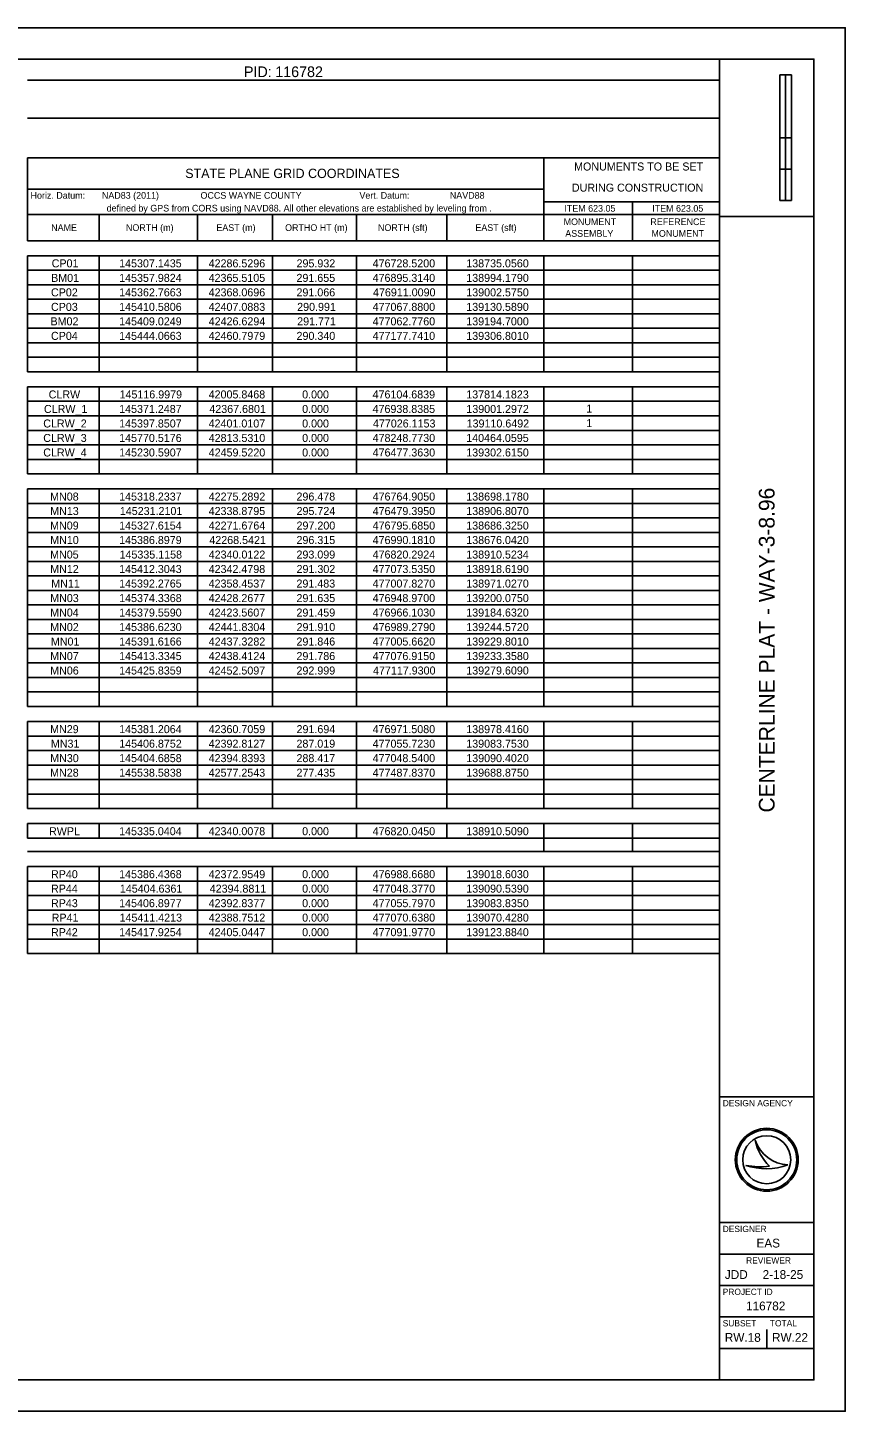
# Model space of a CAD drawing. Extents: x 0 to 34, y 0 to 22.
# Drawn here: x 21 to 34, y 0 to 22 of the extents above; entities that cross this region are included whole.
import ezdxf

# ---------------------------------------------------------------- set-up
doc = ezdxf.new("R2010")
doc.units = 0
for name, color, linetype in [('SH_Border', 7, 'Continuous'), ('SH_Cut_Line', 7, 'Continuous'), ('SH_Data', 7, 'Continuous'), ('SH_Text', 7, 'Continuous')]:
    doc.layers.add(name, color=color, linetype=linetype)

msp = doc.modelspace()

# ---------------------------------------------------------------- linework, layer by layer
at = {"layer": 'SH_Border'}
for p, q in [((32, 0.5), (32, 21.5)), ((32, 19), (33.5, 19)), ((32, 5), (33.5, 5)), ((32, 3), (33.5, 3)), ((32, 2.5), (33.5, 2.5)), ((32, 2), (33.5, 2)), ((32, 1.5), (33.5, 1.5)), ((32, 1), (33.5, 1))]:
    msp.add_line(p, q, dxfattribs=at)
msp.add_lwpolyline([(1.5, 21.5), (33.5, 21.5), (33.5, 0.5), (1.5, 0.5)], close=True, dxfattribs=at)
at = {"layer": 'SH_Cut_Line'}
msp.add_lwpolyline([(0, 0), (34, 0), (34, 22), (0, 22)], close=True, dxfattribs=at)
at = {"layer": 'SH_Data'}
for p, q in [((32.957, 19.25), (32.957, 21.25)), ((33.144, 21.25), (32.957, 21.25)), ((32.957, 20.25), (32.957, 21.25)), ((32.957, 21.25), (33.05, 21.25)), ((33.05, 21.25), (33.051, 21.25)), ((33.051, 21.25), (33.051, 20.25)), ((33.144, 21.25), (33.144, 19.25)), ((33.051, 20.25), (32.957, 20.25)), ((33.143, 20.25), (33.05, 20.25)), ((33.05, 20.25), (33.05, 19.75)), ((33.143, 19.75), (33.143, 20.25)), ((33.05, 19.75), (32.957, 19.75)), ((32.957, 19.75), (32.957, 19.25)), ((33.05, 19.75), (33.143, 19.75)), ((33.05, 19.25), (33.05, 19.75)), ((33.144, 19.25), (32.957, 19.25)), ((32.957, 19.25), (33.05, 19.25)), ((32.567, 4.31), (32.567, 4.31)), ((32.75, 4), (32.75, 4)), ((32.417, 3.91), (32.417, 3.91)), ((33.087, 3.919), (33.087, 3.919)), ((32.75, 1), (32.75, 1.3))]:
    msp.add_line(p, q, dxfattribs=at)
for radius in [0.5, 0.477, 0.477, 0.382]:
    msp.add_circle((32.75, 4), radius, dxfattribs=at)
for centre, radius, start, end in [((33.116, 4.498), 0.58, 198.9257, 198.9319), ((33.347, 4.47), 0.796, 191.6379, 191.6421), ((33.116, 4.498), 0.58, 198.9319, 267.1657), ((33.347, 4.47), 0.796, 191.6421, 226.0947), ((32.739, 4.87), 1.013, 251.4576, 290.0832), ((32.648, 5.154), 1.266, 259.4964, 259.4995), ((32.739, 4.87), 1.013, 251.4527, 251.4576), ((32.648, 5.154), 1.266, 259.4995, 276.6672)]:
    msp.add_arc(centre, radius, start, end, dxfattribs=at)
at = {"layer": 'SH_Text'}
for p, q in [((20.997, 21.168), (22.132, 21.168)), ((22.132, 21.168), (32, 21.168)), ((32, 21.168), (32, 19.932)), ((20.997, 20.559), (22.132, 20.559)), ((22.132, 20.559), (32, 20.559)), ((20.997, 19.932), (22.132, 19.932)), ((20.997, 19.932), (20.997, 19.028)), ((22.132, 19.932), (32, 19.932)), ((29.205, 19.932), (29.205, 19.028)), ((32, 19.932), (32, 19.028)), ((20.997, 19.434), (22.132, 19.434)), ((22.132, 19.434), (29.205, 19.434)), ((29.205, 19.231), (32, 19.231)), ((30.617, 19.231), (30.617, 19.028)), ((20.997, 19.028), (22.132, 19.028)), ((20.997, 19.028), (20.997, 18.613)), ((22.132, 19.028), (32, 19.028)), ((22.132, 19.028), (22.132, 18.613)), ((23.699, 19.028), (23.699, 18.613)), ((24.889, 19.028), (24.889, 18.613)), ((26.226, 19.028), (26.226, 18.613)), ((27.665, 19.028), (27.665, 18.613)), ((29.205, 19.028), (29.205, 18.613)), ((30.617, 19.028), (30.617, 18.613)), ((32, 19.028), (32, 17.451)), ((20.997, 18.613), (22.132, 18.613)), ((22.132, 18.613), (32, 18.613)), ((20.997, 18.373), (22.132, 18.373)), ((20.997, 18.373), (20.997, 17.451)), ((22.132, 18.373), (32, 18.373)), ((22.132, 18.373), (22.132, 17.451)), ((23.699, 18.373), (23.699, 17.451)), ((24.889, 18.373), (24.889, 17.451)), ((26.226, 18.373), (26.226, 17.451)), ((27.665, 18.373), (27.665, 17.451)), ((29.205, 18.373), (29.205, 17.451)), ((30.617, 18.373), (30.617, 17.451)), ((20.997, 18.143), (22.132, 18.143)), ((22.132, 18.143), (32, 18.143)), ((20.997, 17.912), (22.132, 17.912)), ((22.132, 17.912), (32, 17.912)), ((20.997, 17.682), (22.132, 17.682)), ((22.132, 17.682), (32, 17.682)), ((20.997, 17.451), (22.132, 17.451)), ((20.997, 17.451), (20.997, 16.529)), ((22.132, 17.451), (32, 17.451)), ((22.132, 17.451), (22.132, 16.529)), ((23.699, 17.451), (23.699, 16.529)), ((24.889, 17.451), (24.889, 16.529)), ((26.226, 17.451), (26.226, 16.529)), ((27.665, 17.451), (27.665, 16.529)), ((29.205, 17.451), (29.205, 16.529)), ((30.617, 17.451), (30.617, 16.529)), ((32, 17.451), (32, 16.289)), ((20.997, 17.221), (22.132, 17.221)), ((22.132, 17.221), (32, 17.221)), ((20.997, 16.99), (22.132, 16.99)), ((22.132, 16.99), (32, 16.99)), ((20.997, 16.759), (22.132, 16.759)), ((22.132, 16.759), (32, 16.759)), ((20.997, 16.529), (22.132, 16.529)), ((22.132, 16.529), (32, 16.529)), ((20.997, 16.289), (22.132, 16.289)), ((20.997, 16.289), (20.997, 14.906)), ((22.132, 16.289), (32, 16.289)), ((22.132, 16.289), (22.132, 14.906)), ((23.699, 16.289), (23.699, 14.906)), ((24.889, 16.289), (24.889, 14.906)), ((26.226, 16.289), (26.226, 14.906)), ((27.665, 16.289), (27.665, 14.906)), ((29.205, 16.289), (29.205, 14.906)), ((30.617, 16.289), (30.617, 14.906)), ((32, 16.289), (32, 10.967)), ((20.997, 16.059), (22.132, 16.059)), ((22.132, 16.059), (32, 16.059)), ((20.997, 15.828), (22.132, 15.828)), ((22.132, 15.828), (32, 15.828)), ((20.997, 15.597), (22.132, 15.597)), ((22.132, 15.597), (32, 15.597)), ((20.997, 15.367), (22.132, 15.367)), ((22.132, 15.367), (32, 15.367)), ((20.997, 15.136), (22.132, 15.136)), ((22.132, 15.136), (32, 15.136)), ((20.997, 14.906), (22.132, 14.906)), ((22.132, 14.906), (32, 14.906)), ((20.997, 14.666), (22.132, 14.666)), ((20.997, 14.666), (20.997, 11.207)), ((22.132, 14.666), (32, 14.666)), ((22.132, 14.666), (22.132, 11.207)), ((23.699, 14.666), (23.699, 11.207)), ((24.889, 14.666), (24.889, 11.207)), ((26.226, 14.666), (26.226, 11.207)), ((27.665, 14.666), (27.665, 11.207)), ((29.205, 14.666), (29.205, 11.207)), ((30.617, 14.666), (30.617, 11.207)), ((20.997, 14.435), (22.132, 14.435)), ((22.132, 14.435), (32, 14.435)), ((20.997, 14.205), (22.132, 14.205)), ((22.132, 14.205), (32, 14.205)), ((20.997, 13.974), (22.132, 13.974)), ((22.132, 13.974), (32, 13.974)), ((20.997, 13.744), (22.132, 13.744)), ((22.132, 13.744), (32, 13.744)), ((20.997, 13.513), (22.132, 13.513)), ((22.132, 13.513), (32, 13.513)), ((20.997, 13.282), (22.132, 13.282)), ((22.132, 13.282), (32, 13.282)), ((20.997, 13.052), (22.132, 13.052)), ((22.132, 13.052), (32, 13.052)), ((20.997, 12.821), (22.132, 12.821)), ((22.132, 12.821), (32, 12.821)), ((20.997, 12.591), (22.132, 12.591)), ((22.132, 12.591), (32, 12.591)), ((20.997, 12.36), (22.132, 12.36)), ((22.132, 12.36), (32, 12.36)), ((20.997, 12.13), (22.132, 12.13)), ((22.132, 12.13), (32, 12.13)), ((20.997, 11.899), (22.132, 11.899)), ((22.132, 11.899), (32, 11.899)), ((20.997, 11.668), (22.132, 11.668)), ((22.132, 11.668), (32, 11.668)), ((20.997, 11.438), (22.132, 11.438)), ((22.132, 11.438), (32, 11.438)), ((20.997, 11.207), (22.132, 11.207)), ((22.132, 11.207), (32, 11.207)), ((20.997, 10.967), (22.132, 10.967)), ((20.997, 10.967), (20.997, 9.584)), ((22.132, 10.967), (32, 10.967)), ((22.132, 10.967), (22.132, 9.584)), ((23.699, 10.967), (23.699, 9.584)), ((24.889, 10.967), (24.889, 9.584)), ((26.226, 10.967), (26.226, 9.584)), ((27.665, 10.967), (27.665, 9.584)), ((29.205, 10.967), (29.205, 9.584)), ((30.617, 10.967), (30.617, 9.584)), ((32, 10.967), (32, 7.278)), ((20.997, 10.737), (22.132, 10.737)), ((22.132, 10.737), (32, 10.737)), ((20.997, 10.506), (22.132, 10.506)), ((22.132, 10.506), (32, 10.506)), ((20.997, 10.276), (22.132, 10.276)), ((22.132, 10.276), (32, 10.276)), ((20.997, 10.045), (22.132, 10.045)), ((22.132, 10.045), (32, 10.045)), ((20.997, 9.815), (22.132, 9.815)), ((22.132, 9.815), (32, 9.815)), ((20.997, 9.584), (22.132, 9.584)), ((22.132, 9.584), (32, 9.584)), ((20.997, 9.344), (22.132, 9.344)), ((20.997, 9.344), (20.997, 9.114)), ((22.132, 9.344), (32, 9.344)), ((22.132, 9.344), (22.132, 9.114)), ((23.699, 9.344), (23.699, 9.114)), ((24.889, 9.344), (24.889, 9.114)), ((26.226, 9.344), (26.226, 9.114)), ((27.665, 9.344), (27.665, 9.114)), ((29.205, 9.344), (29.205, 8.902)), ((30.617, 9.344), (30.617, 8.902)), ((20.997, 9.114), (22.132, 9.114)), ((22.132, 9.114), (32, 9.114)), ((20.997, 8.902), (22.132, 8.902)), ((22.132, 8.902), (32, 8.902)), ((20.997, 8.662), (22.132, 8.662)), ((20.997, 8.662), (20.997, 7.278)), ((22.132, 8.662), (32, 8.662)), ((22.132, 8.662), (22.132, 7.278)), ((23.699, 8.662), (23.699, 7.278)), ((24.889, 8.662), (24.889, 7.278)), ((26.226, 8.662), (26.226, 7.278)), ((27.665, 8.662), (27.665, 7.278)), ((29.205, 8.662), (29.205, 7.278)), ((30.617, 8.662), (30.617, 7.278)), ((20.997, 8.431), (22.132, 8.431)), ((22.132, 8.431), (32, 8.431)), ((20.997, 8.201), (22.132, 8.201)), ((22.132, 8.201), (32, 8.201)), ((20.997, 7.97), (22.132, 7.97)), ((22.132, 7.97), (32, 7.97)), ((20.997, 7.739), (22.132, 7.739)), ((22.132, 7.739), (32, 7.739)), ((20.997, 7.509), (22.132, 7.509)), ((22.132, 7.509), (32, 7.509)), ((20.997, 7.278), (22.132, 7.278)), ((22.132, 7.278), (32, 7.278))]:
    msp.add_line(p, q, dxfattribs=at)

# ---------------------------------------------------------------- texts
at = {"layer": 'SH_Data'}
msp.add_text('CENTERLINE PLAT - WAY-3-8.96', height=0.25, rotation=90, dxfattribs=at).set_placement((32.875, 9.521))
for s, height, p in [('DESIGN AGENCY', 0.1, (32.05, 4.85)), ('DESIGNER', 0.1, (32.05, 2.85)), ('EAS', 0.14, (32.587, 2.605)), ('REVIEWER', 0.1, (32.422, 2.35)), ('JDD', 0.14, (32.084, 2.105)), ('2-18-25', 0.14, (32.685, 2.105)), ('PROJECT ID', 0.1, (32.05, 1.85)), ('116782', 0.14, (32.421, 1.605)), ('SUBSET', 0.1, (32.05, 1.35)), ('TOTAL', 0.1, (32.8, 1.35)), ('RW.18', 0.14, (32.083, 1.105)), ('RW.22', 0.14, (32.834, 1.105))]:
    msp.add_text(s, height=height, dxfattribs=at).set_placement(p)
at = {"layer": 'SH_Text'}
for s, height, p in [('PID:', 0.1697, (24.437, 21.214)), ('116782', 0.1697, (24.935, 21.214)), ('  MONUMENTS TO BE SET', 0.12728, (29.592, 19.729)), ('STATE PLANE GRID COORDINATES', 0.14849, (23.503, 19.609)), ('Horiz. Datum:', 0.10606, (21.043, 19.28)), ('NAD83 (2011)', 0.10606, (22.178, 19.28)), ('OCCS WAYNE COUNTY', 0.10606, (23.746, 19.28)), ('Vert. Datum:', 0.10606, (26.273, 19.28)), ('NAVD88', 0.1061, (27.711, 19.28)), (' DURING CONSTRUCTION', 0.12728, (29.604, 19.393)), (' defined by GPS from CORS using NAVD88. All other elevations are established by leveling from .', 0.10606, (22.214, 19.077)), ('ITEM 623.05', 0.10606, (29.532, 19.074)), ('ITEM 623.05', 0.10606, (30.929, 19.074)), ('MONUMENT ', 0.1061, (29.52, 18.861)), ('REFERENCE ', 0.1061, (30.9, 18.861)), ('NAME', 0.1061, (21.371, 18.768)), ('NORTH (m)', 0.1061, (22.56, 18.768)), ('EAST (m)', 0.1061, (23.998, 18.768)), ('ORTHO HT (m)', 0.10606, (25.091, 18.768)), ('NORTH (sft)', 0.10606, (26.568, 18.768)), ('EAST (sft)', 0.1061, (28.117, 18.768)), ('ASSEMBLY', 0.1061, (29.546, 18.675)), ('MONUMENT', 0.1061, (30.917, 18.675)), ('CP01', 0.1273, (21.379, 18.189)), ('145307.1435', 0.12728, (22.452, 18.189)), ('42286.5296', 0.1273, (23.875, 18.189)), ('295.932', 0.1273, (25.273, 18.189)), ('476728.5200', 0.12728, (26.483, 18.189)), ('138735.0560', 0.12728, (27.972, 18.189)), ('BM01', 0.1273, (21.37, 17.958)), ('145357.9824', 0.12728, (22.452, 17.958)), ('42365.5105', 0.1273, (23.875, 17.958)), ('291.655', 0.1273, (25.272, 17.958)), ('476895.3140', 0.12728, (26.483, 17.958)), ('138994.1790', 0.12728, (27.972, 17.958)), ('CP02', 0.1273, (21.368, 17.728)), ('145362.7663', 0.12728, (22.452, 17.728)), ('42368.0696', 0.1273, (23.875, 17.728)), ('291.066', 0.1273, (25.272, 17.728)), ('476911.0090', 0.12728, (26.489, 17.728)), ('139002.5750', 0.12728, (27.972, 17.728)), ('CP03', 0.1273, (21.368, 17.497)), ('145410.5806', 0.12728, (22.452, 17.497)), ('42407.0883', 0.1273, (23.875, 17.497)), ('290.991', 0.1273, (25.283, 17.497)), ('477067.8800', 0.12728, (26.483, 17.497)), ('139130.5890', 0.12728, (27.972, 17.497)), ('BM02', 0.1273, (21.36, 17.267)), ('145409.0249', 0.12728, (22.452, 17.267)), ('42426.6294', 0.1273, (23.876, 17.267)), ('291.771', 0.1273, (25.283, 17.267)), ('477062.7760', 0.12728, (26.483, 17.267)), ('139194.7000', 0.12728, (27.972, 17.267)), ('CP04', 0.1273, (21.368, 17.036)), ('145444.0663', 0.12728, (22.452, 17.036)), ('42460.7979', 0.1273, (23.875, 17.036)), ('290.340', 0.1273, (25.273, 17.036)), ('477177.7410', 0.12728, (26.483, 17.036)), ('139306.8010', 0.12728, (27.972, 17.036)), ('CLRW', 0.1273, (21.331, 16.105)), ('145116.9979', 0.12728, (22.458, 16.105)), ('42005.8468', 0.1273, (23.875, 16.105)), ('0.000', 0.1273, (25.362, 16.105)), ('476104.6839', 0.12728, (26.482, 16.105)), ('137814.1823', 0.12728, (27.972, 16.105)), ('CLRW_1', 0.1273, (21.256, 15.874)), ('145371.2487', 0.12728, (22.452, 15.874)), ('42367.6801', 0.1273, (23.886, 15.874)), ('0.000', 0.1273, (25.362, 15.874)), ('476938.8385', 0.12728, (26.482, 15.874)), ('139001.2972', 0.12728, (27.973, 15.874)), ('1', 0.127, (29.881, 15.88)), ('CLRW_2', 0.1273, (21.245, 15.643)), ('145397.8507', 0.12728, (22.452, 15.643)), ('42401.0107', 0.1273, (23.875, 15.643)), ('0.000', 0.1273, (25.362, 15.643)), ('477026.1153', 0.12728, (26.488, 15.643)), ('139110.6492', 0.12728, (27.978, 15.643)), ('1', 0.127, (29.881, 15.649)), ('CLRW_3', 0.1273, (21.245, 15.413)), ('145770.5176', 0.12728, (22.452, 15.413)), ('42813.5310', 0.1273, (23.876, 15.413)), ('0.000', 0.1273, (25.362, 15.413)), ('478248.7730', 0.12728, (26.483, 15.413)), ('140464.0595', 0.12728, (27.971, 15.413)), ('CLRW_4', 0.1273, (21.245, 15.182)), ('145230.5907', 0.12728, (22.452, 15.182)), ('42459.5220', 0.1273, (23.876, 15.182)), ('0.000', 0.1273, (25.362, 15.182)), ('476477.3630', 0.12728, (26.483, 15.182)), ('139302.6150', 0.12728, (27.972, 15.182)), ('MN08', 0.1273, (21.354, 14.481)), ('145318.2337', 0.12728, (22.452, 14.481)), ('42275.2892', 0.1273, (23.876, 14.481)), ('296.478', 0.1273, (25.272, 14.481)), ('476764.9050', 0.12728, (26.483, 14.481)), ('138698.1780', 0.12728, (27.972, 14.481)), ('MN13', 0.1273, (21.355, 14.251)), ('145231.2101', 0.12728, (22.463, 14.251)), ('42338.8795', 0.1273, (23.875, 14.251)), ('295.724', 0.1273, (25.273, 14.251)), ('476479.3950', 0.12728, (26.483, 14.251)), ('138906.8070', 0.12728, (27.972, 14.251)), ('MN09', 0.1273, (21.354, 14.02)), ('145327.6154', 0.12728, (22.452, 14.02)), ('42271.6764', 0.1273, (23.876, 14.02)), ('297.200', 0.1273, (25.273, 14.02)), ('476795.6850', 0.12728, (26.483, 14.02)), ('138686.3250', 0.12728, (27.972, 14.02)), ('MN10', 0.1273, (21.355, 13.79)), ('145386.8979', 0.12728, (22.452, 13.79)), ('42268.5421', 0.1273, (23.886, 13.79)), ('296.315', 0.1273, (25.272, 13.79)), ('476990.1810', 0.12728, (26.483, 13.79)), ('138676.0420', 0.12728, (27.972, 13.79)), ('MN05', 0.1273, (21.354, 13.559)), ('145335.1158', 0.12728, (22.458, 13.559)), ('42340.0122', 0.1273, (23.876, 13.559)), ('293.099', 0.1273, (25.272, 13.559)), ('476820.2924', 0.12728, (26.483, 13.559)), ('138910.5234', 0.12728, (27.972, 13.559)), ('MN12', 0.1273, (21.355, 13.329)), ('145412.3043', 0.12728, (22.452, 13.329)), ('42342.4798', 0.1273, (23.875, 13.329)), ('291.302', 0.1273, (25.273, 13.329)), ('477073.5350', 0.12728, (26.483, 13.329)), ('138918.6190', 0.12728, (27.972, 13.329)), ('MN11', 0.1273, (21.372, 13.098)), ('145392.2765', 0.12728, (22.452, 13.098)), ('42358.4537', 0.1273, (23.875, 13.098)), ('291.483', 0.1273, (25.272, 13.098)), ('477007.8270', 0.12728, (26.483, 13.098)), ('138971.0270', 0.12728, (27.972, 13.098)), ('MN03', 0.1273, (21.355, 12.867)), ('145374.3368', 0.12728, (22.452, 12.867)), ('42428.2677', 0.1273, (23.875, 12.867)), ('291.635', 0.1273, (25.272, 12.867)), ('476948.9700', 0.12728, (26.483, 12.867)), ('139200.0750', 0.12728, (27.972, 12.867)), ('MN04', 0.1273, (21.355, 12.637)), ('145379.5590', 0.12728, (22.452, 12.637)), ('42423.5607', 0.1273, (23.875, 12.637)), ('291.459', 0.1273, (25.272, 12.637)), ('476966.1030', 0.12728, (26.483, 12.637)), ('139184.6320', 0.12728, (27.972, 12.637)), ('MN02', 0.1273, (21.355, 12.406)), ('145386.6230', 0.12728, (22.452, 12.406)), ('42441.8304', 0.1273, (23.876, 12.406)), ('291.910', 0.1273, (25.273, 12.406)), ('476989.2790', 0.12728, (26.483, 12.406)), ('139244.5720', 0.12728, (27.972, 12.406)), ('MN01', 0.1273, (21.366, 12.176)), ('145391.6166', 0.12728, (22.452, 12.176)), ('42437.3282', 0.1273, (23.876, 12.176)), ('291.846', 0.1273, (25.272, 12.176)), ('477005.6620', 0.12728, (26.483, 12.176)), ('139229.8010', 0.12728, (27.972, 12.176)), ('MN07', 0.1273, (21.355, 11.945)), ('145413.3345', 0.12728, (22.452, 11.945)), ('42438.4124', 0.1273, (23.876, 11.945)), ('291.786', 0.1273, (25.272, 11.945)), ('477076.9150', 0.12728, (26.483, 11.945)), ('139233.3580', 0.12728, (27.972, 11.945)), ('MN06', 0.1273, (21.355, 11.715)), ('145425.8359', 0.12728, (22.452, 11.715)), ('42452.5097', 0.1273, (23.875, 11.715)), ('292.999', 0.1273, (25.272, 11.715)), ('477117.9300', 0.12728, (26.489, 11.715)), ('139279.6090', 0.12728, (27.972, 11.715)), ('MN29', 0.1273, (21.354, 10.783)), ('145381.2064', 0.12728, (22.452, 10.783)), ('42360.7059', 0.1273, (23.875, 10.783)), ('291.694', 0.1273, (25.273, 10.783)), ('476971.5080', 0.12728, (26.483, 10.783)), ('138978.4160', 0.12728, (27.972, 10.783)), ('MN31', 0.1273, (21.366, 10.552)), ('145406.8752', 0.12728, (22.453, 10.552)), ('42392.8127', 0.1273, (23.875, 10.552)), ('287.019', 0.1273, (25.272, 10.552)), ('477055.7230', 0.12728, (26.483, 10.552)), ('139083.7530', 0.12728, (27.972, 10.552)), ('MN30', 0.1273, (21.355, 10.322)), ('145404.6858', 0.12728, (22.452, 10.322)), ('42394.8393', 0.1273, (23.875, 10.322)), ('288.417', 0.1273, (25.272, 10.322)), ('477048.5400', 0.12728, (26.483, 10.322)), ('139090.4020', 0.12728, (27.972, 10.322)), ('MN28', 0.1273, (21.354, 10.091)), ('145538.5838', 0.12728, (22.452, 10.091)), ('42577.2543', 0.1273, (23.875, 10.091)), ('277.435', 0.1273, (25.272, 10.091)), ('477487.8370', 0.12728, (26.483, 10.091)), ('139688.8750', 0.12728, (27.972, 10.091)), ('RWPL', 0.1273, (21.337, 9.16)), ('145335.0404', 0.12728, (22.452, 9.16)), ('42340.0078', 0.1273, (23.875, 9.16)), ('0.000', 0.1273, (25.362, 9.16)), ('476820.0450', 0.12728, (26.483, 9.16)), ('138910.5090', 0.12728, (27.972, 9.16)), ('RP40', 0.1273, (21.368, 8.477)), ('145386.4368', 0.12728, (22.452, 8.477)), ('42372.9549', 0.1273, (23.875, 8.477)), ('0.000', 0.1273, (25.362, 8.477)), ('476988.6680', 0.12728, (26.483, 8.477)), ('139018.6030', 0.12728, (27.972, 8.477)), ('RP44', 0.1273, (21.368, 8.247)), ('145404.6361', 0.12728, (22.463, 8.247)), ('42394.8811', 0.1273, (23.892, 8.247)), ('0.000', 0.1273, (25.362, 8.247)), ('477048.3770', 0.12728, (26.483, 8.247)), ('139090.5390', 0.12728, (27.972, 8.247)), ('RP43', 0.1273, (21.368, 8.016)), ('145406.8977', 0.12728, (22.452, 8.016)), ('42392.8377', 0.1273, (23.875, 8.016)), ('0.000', 0.1273, (25.362, 8.016)), ('477055.7970', 0.12728, (26.483, 8.016)), ('139083.8350', 0.12728, (27.972, 8.016)), ('RP41', 0.1273, (21.379, 7.786)), ('145411.4213', 0.12728, (22.458, 7.786)), ('42388.7512', 0.1273, (23.876, 7.786)), ('0.000', 0.1273, (25.362, 7.786)), ('477070.6380', 0.12728, (26.483, 7.786)), ('139070.4280', 0.12728, (27.972, 7.786)), ('RP42', 0.1273, (21.368, 7.555)), ('145417.9254', 0.12728, (22.452, 7.555)), ('42405.0447', 0.1273, (23.875, 7.555)), ('0.000', 0.1273, (25.362, 7.555)), ('477091.9770', 0.12728, (26.483, 7.555)), ('139123.8840', 0.12728, (27.972, 7.555))]:
    msp.add_text(s, height=height, dxfattribs=at).set_placement(p)

doc.saveas('drawing.dxf')
